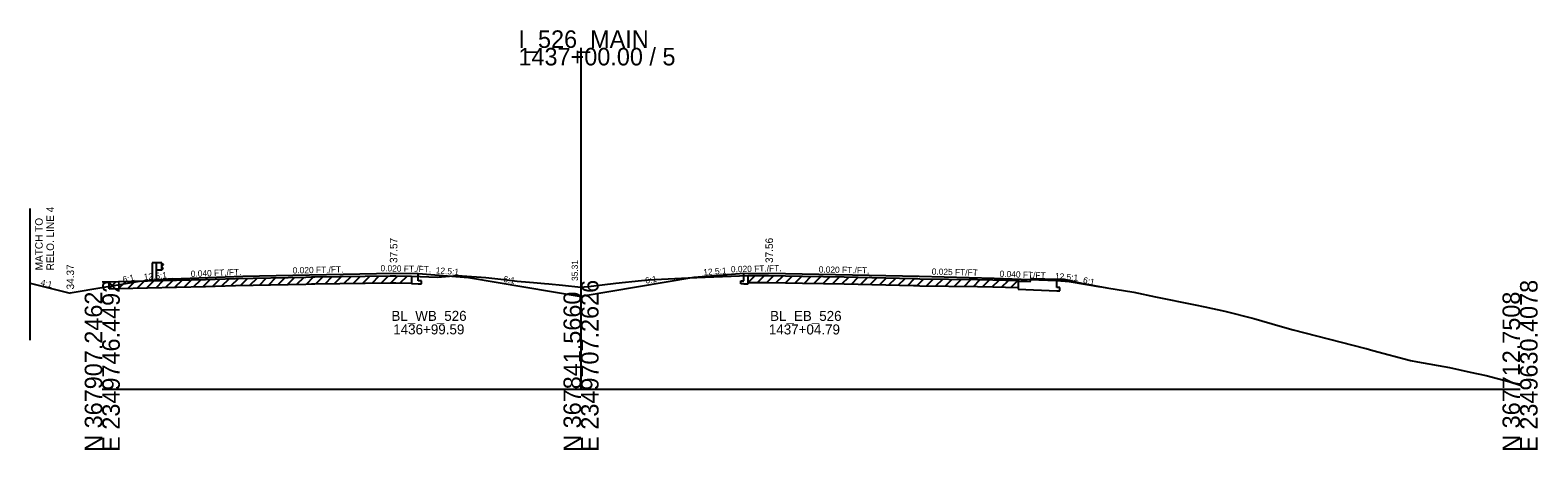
# Model space of a CAD drawing. Extents: x -170 to 2527928, y -10 to 1619750.
# Drawn here: x 4988.5 to 5229.3, y 2490.3 to 2557.4 of the extents above; entities that cross this region are included whole.
import ezdxf

# ---------------------------------------------------------------- set-up
doc = ezdxf.new("R2010")
doc.units = 0
for name, color, linetype in [('RD_GPK_XS_Cell', 7, 'Continuous'), ('RD_XS_Base', 7, 'Continuous'), ('RD_XS_EarthShd', 7, 'Continuous'), ('RD_XS_ExGround', 7, 'Continuous'), ('RD_XS_ExPaveRet', 7, 'Continuous'), ('RD_XS_GR', 7, 'Continuous'), ('RD_XS_MatchLine', 7, 'Continuous'), ('RD_XS_Pave', 7, 'Continuous'), ('RD_XS_PaveShd', 7, 'Continuous'), ('RD_XS_TieSlope', 7, 'Continuous'), ('RD_XS_TX_Elev_EX', 7, 'Continuous'), ('RD_XS_TX_Slope', 7, 'Continuous'), ('RD_XS_TX_Station', 7, 'Continuous')]:
    doc.layers.add(name, color=color, linetype=linetype)

msp = doc.modelspace()

# ---------------------------------------------------------------- linework, layer by layer
at = {"layer": 'RD_GPK_XS_Cell'}
for p, q in [((5076.48, 2500), (5076.48, 2554.57)), ((5000, 2500), (5076.48, 2500)), ((5076.48, 2500), (5226.48, 2500))]:
    msp.add_line(p, q, dxfattribs=at)
at = {"layer": 'RD_XS_Base'}
for p, q in [((5049.39, 2516.88), (5049.39, 2516.97)), ((5049.39, 2516.88), (5050.48, 2516.85)), ((5050.48, 2517.35), (5050.48, 2518.49)), ((5050.98, 2517.34), (5050.48, 2517.35)), ((5050.48, 2516.85), (5050.98, 2516.84)), ((5050.98, 2516.84), (5050.98, 2517.34)), ((5101.98, 2517.34), (5102.48, 2517.35)), ((5101.98, 2516.84), (5101.98, 2517.34)), ((5102.48, 2516.85), (5101.98, 2516.84)), ((5102.48, 2517.35), (5102.48, 2518.48)), ((5102.48, 2516.85), (5103.16, 2516.86)), ((5103.16, 2516.86), (5103.16, 2518.16)), ((5146.32, 2517.63), (5146.32, 2515.99)), ((5152.48, 2516.25), (5152.48, 2517.38)), ((5146.32, 2515.99), (5152.48, 2515.75)), ((5152.98, 2516.24), (5152.48, 2516.25)), ((5152.48, 2515.75), (5152.98, 2515.74)), ((5152.98, 2515.74), (5152.98, 2516.24))]:
    msp.add_line(p, q, dxfattribs=at)
at = {"layer": 'RD_XS_EarthShd'}
for p, q in [((5009.71, 2517.52), (5005.96, 2517.22)), ((5011.21, 2517.64), (5009.71, 2517.52)), ((5050.48, 2518.49), (5058.48, 2517.85)), ((5102.48, 2518.48), (5094.48, 2517.84))]:
    msp.add_line(p, q, dxfattribs=at)
at = {"layer": 'RD_XS_ExGround'}
msp.add_lwpolyline([(5000, 2517.17), (5002.59, 2517.22), (5016.51, 2517.53), (5018.01, 2517.59), (5021.3, 2517.71), (5032.5, 2517.93), (5033.41, 2517.95), (5033.97, 2517.96), (5046, 2518.14), (5046.9, 2518.13), (5049.39, 2518.09), (5053.57, 2517.91), (5056.75, 2518.16), (5061.25, 2517.85), (5064.63, 2517.5), (5066.26, 2517.3), (5068.24, 2517.12), (5068.88, 2517.07), (5070.66, 2516.9), (5071.34, 2516.84), (5073.5, 2516.62), (5076.45, 2516.31), (5078.1, 2516.5), (5082.05, 2516.96), (5086.15, 2517.39), (5087.23, 2517.5), (5093.59, 2517.8), (5103.16, 2518.16), (5104.96, 2518.18), (5106.44, 2518.19), (5111.87, 2518.09), (5118.52, 2517.96), (5129.6, 2517.7), (5130.29, 2517.68), (5130.62, 2517.67), (5139.81, 2517.54), (5142.27, 2517.47), (5146.33, 2517.36), (5146.47, 2517.3), (5146.53, 2517.28), (5147.75, 2517.26), (5148.24, 2517.25), (5148.36, 2517.58), (5148.41, 2517.71), (5148.52, 2517.71), (5148.8, 2517.71), (5152.38, 2517.58), (5153.64, 2517.58), (5156.44, 2516.96), (5160.48, 2516.2), (5164.8, 2515.52), (5168.26, 2514.78), (5174.56, 2513.51), (5176.1, 2513.15), (5179.33, 2512.5), (5183.93, 2511.29), (5188.17, 2510.07), (5190.24, 2509.5), (5201.62, 2506.56), (5201.82, 2506.51), (5201.91, 2506.49), (5202.94, 2506.21), (5208.97, 2504.61), (5210.08, 2504.38), (5215.19, 2503.5), (5218.5, 2502.75), (5221.04, 2502.17), (5224.71, 2501.24), (5226.48, 2500.67)], dxfattribs=at)
at = {"layer": 'RD_XS_ExPaveRet'}
for p, q in [((5001.1, 2516.07), (5002.24, 2517.21)), ((5001.1, 2516.07), (5001.1, 2517.19)), ((5002.6, 2516.1), (5003.75, 2517.25)), ((5004.1, 2516.13), (5005.25, 2517.28)), ((5005.6, 2516.17), (5006.75, 2517.31)), ((5007.1, 2516.2), (5008.25, 2517.35)), ((5008.6, 2516.23), (5009.75, 2517.38)), ((5010.1, 2516.27), (5011.25, 2517.41)), ((5011.6, 2516.3), (5012.75, 2517.45)), ((5013.1, 2516.33), (5014.25, 2517.48)), ((5014.6, 2516.37), (5015.75, 2517.51)), ((5016.1, 2516.4), (5017.26, 2517.56)), ((5017.6, 2516.45), (5018.76, 2517.62)), ((5019.1, 2516.51), (5020.26, 2517.67)), ((5020.6, 2516.56), (5021.76, 2517.71)), ((5021.3, 2516.58), (5032.5, 2516.81)), ((5022.1, 2516.6), (5023.24, 2517.75)), ((5023.6, 2516.63), (5024.74, 2517.78)), ((5025.1, 2516.66), (5026.24, 2517.81)), ((5026.6, 2516.69), (5027.74, 2517.84)), ((5028.1, 2516.72), (5029.24, 2517.87)), ((5029.6, 2516.75), (5030.74, 2517.9)), ((5031.1, 2516.78), (5032.24, 2517.93)), ((5032.5, 2516.81), (5033.41, 2516.83)), ((5032.6, 2516.82), (5033.74, 2517.96)), ((5033.41, 2516.83), (5033.97, 2516.84)), ((5033.97, 2516.84), (5046, 2517.02)), ((5034.1, 2516.84), (5035.24, 2517.98)), ((5035.6, 2516.86), (5036.74, 2518)), ((5037.1, 2516.89), (5038.24, 2518.03)), ((5038.6, 2516.91), (5039.74, 2518.05)), ((5040.1, 2516.93), (5041.24, 2518.07)), ((5041.6, 2516.95), (5042.74, 2518.09)), ((5043.1, 2516.98), (5044.24, 2518.12)), ((5044.6, 2517), (5045.74, 2518.14)), ((5046, 2517.02), (5046.9, 2517.01)), ((5046.1, 2517.02), (5047.2, 2518.12)), ((5046.9, 2517.01), (5049.39, 2516.97)), ((5047.6, 2517), (5048.7, 2518.1)), ((5049.39, 2518.09), (5049.39, 2516.97)), ((5103.16, 2517.04), (5104.29, 2518.17)), ((5103.16, 2517.04), (5103.16, 2518.16)), ((5103.16, 2517.04), (5104.96, 2517.06)), ((5104.66, 2517.06), (5105.79, 2518.19)), ((5104.96, 2517.06), (5106.44, 2517.07)), ((5106.16, 2517.07), (5107.27, 2518.17)), ((5106.44, 2517.07), (5111.87, 2516.97)), ((5107.66, 2517.05), (5108.76, 2518.15)), ((5109.16, 2517.02), (5110.26, 2518.12)), ((5110.66, 2516.99), (5111.76, 2518.09)), ((5111.87, 2516.97), (5118.52, 2516.84)), ((5112.16, 2516.96), (5113.26, 2518.06)), ((5113.66, 2516.93), (5114.76, 2518.03)), ((5115.16, 2516.9), (5116.26, 2518)), ((5116.66, 2516.87), (5117.76, 2517.97)), ((5118.16, 2516.84), (5119.26, 2517.94)), ((5118.52, 2516.84), (5129.6, 2516.57)), ((5119.66, 2516.81), (5120.75, 2517.91)), ((5121.16, 2516.78), (5122.25, 2517.87)), ((5122.66, 2516.74), (5123.75, 2517.83)), ((5124.16, 2516.7), (5125.25, 2517.8)), ((5125.66, 2516.67), (5126.75, 2517.76)), ((5127.16, 2516.63), (5128.25, 2517.73)), ((5128.66, 2516.6), (5129.75, 2517.69)), ((5130.16, 2516.56), (5131.26, 2517.66)), ((5131.66, 2516.54), (5132.76, 2517.64)), ((5133.16, 2516.52), (5134.26, 2517.62)), ((5134.66, 2516.49), (5135.76, 2517.6)), ((5136.16, 2516.47), (5137.26, 2517.58)), ((5137.66, 2516.45), (5138.76, 2517.56)), ((5139.16, 2516.43), (5140.26, 2517.53)), ((5140.66, 2516.4), (5141.75, 2517.49)), ((5142.16, 2516.35), (5143.25, 2517.45)), ((5143.66, 2516.31), (5144.75, 2517.4)), ((5145.16, 2516.27), (5146.25, 2517.36)), ((5146.33, 2517.36), (5146.33, 2516.24)), ((5001.1, 2516.07), (5002.59, 2516.1)), ((5002.59, 2516.1), (5016.51, 2516.41)), ((5016.51, 2516.41), (5018.01, 2516.47)), ((5018.01, 2516.47), (5021.3, 2516.58)), ((5129.6, 2516.57), (5130.29, 2516.56)), ((5130.29, 2516.56), (5130.62, 2516.55)), ((5130.62, 2516.55), (5139.81, 2516.42)), ((5139.81, 2516.42), (5142.27, 2516.35)), ((5142.27, 2516.35), (5146.33, 2516.24))]:
    msp.add_line(p, q, dxfattribs=at)
at = {"layer": 'RD_XS_GR'}
for p, q in [((5008.63, 2520.2), (5007.96, 2520.2)), ((5007.96, 2520.2), (5007.96, 2517.4)), ((5009.54, 2520.2), (5008.63, 2520.2)), ((5008.63, 2520.2), (5008.63, 2517.45)), ((5009.54, 2519.03), (5009.54, 2520.2)), ((5009.54, 2520.12), (5009.71, 2519.92)), ((5009.71, 2519.87), (5009.54, 2519.67)), ((5009.71, 2519.35), (5009.54, 2519.55)), ((5009.54, 2519.1), (5009.71, 2519.3)), ((5009.71, 2519.92), (5009.71, 2519.87)), ((5009.71, 2519.3), (5009.71, 2519.35)), ((5009.54, 2519.03), (5008.63, 2519.03))]:
    msp.add_line(p, q, dxfattribs=at)
at = {"layer": 'RD_XS_MatchLine'}
msp.add_line((4988.49, 2507.85), (4988.49, 2528.91), dxfattribs=at)
at = {"layer": 'RD_XS_Pave'}
for p, q in [((5022.48, 2518.09), (5046.48, 2518.57)), ((5106.48, 2518.56), (5130.48, 2518.08)), ((5130.48, 2518.08), (5142.48, 2517.78))]:
    msp.add_line(p, q, dxfattribs=at)
at = {"layer": 'RD_XS_PaveShd'}
for p, q in [((5011.21, 2517.64), (5022.48, 2518.09)), ((5011.21, 2517.43), (5011.21, 2517.64)), ((5046.48, 2518.57), (5050.48, 2518.49)), ((5102.48, 2518.48), (5106.48, 2518.56)), ((5142.48, 2517.78), (5152.48, 2517.38))]:
    msp.add_line(p, q, dxfattribs=at)
at = {"layer": 'RD_XS_TieSlope'}
for p, q in [((4988.48, 2516.96), (4994.85, 2515.37)), ((5005.96, 2517.22), (4994.85, 2515.37)), ((5058.48, 2517.85), (5076.5, 2514.85)), ((5094.48, 2517.84), (5076.5, 2514.85)), ((5152.48, 2517.38), (5154.48, 2517.22)), ((5154.48, 2517.22), (5159.47, 2516.39))]:
    msp.add_line(p, q, dxfattribs=at)

# ---------------------------------------------------------------- texts
at = {"layer": 'RD_GPK_XS_Cell'}
for s, p in [('I_526_MAIN', (5066.48, 2554.57)), ('1437+00.00 / 5', (5066.48, 2551.77))]:
    msp.add_text(s, height=2.8, dxfattribs=at).set_placement(p)
for s, p in [('E 2349746.4492', (5002.8, 2490)), ('E 2349707.2626', (5079.28, 2490)), ('E 2349630.4078', (5229.28, 2490)), ('N 367907.2462', (5000, 2490)), ('N 367841.5660', (5076.48, 2490)), ('N 367712.7508', (5226.48, 2490))]:
    msp.add_text(s, height=2.8, rotation=90, dxfattribs=at).set_placement(p)
at = {"layer": 'RD_XS_TX_Elev_EX'}
msp.add_text('35.31', height=1, rotation=90, dxfattribs=at).set_placement((5075.98, 2517.31))
at = {"layer": 'RD_XS_TX_Slope'}
for s, rotation, p in [('0.040 FT./FT.', 2.2906, (5014.16, 2517.94)), ('0.020 FT./FT.', 1.1458, (5030.43, 2518.5)), ('0.020 FT./FT.', 358.8542, (5044.44, 2518.86)), ('12.5:1', 355.4261, (5053.24, 2518.53)), ('12.5:1', 4.5739, (5096.06, 2518.19)), ('0.020 FT./FT.', 1.1458, (5100.43, 2518.69)), ('0.020 FT./FT.', 358.8542, (5114.44, 2518.66)), ('0.025 FT/FT', 358.5679, (5132.49, 2518.32)), ('4:1', 347.2181, (4990.08, 2516.62)), ('6:1', 12.4816, (5003.38, 2517.01)), ('12.5:1', 4.5739, (5006.66, 2517.45)), ('6:1', 350.5377, (5064.01, 2517.16)), ('6:1', 9.4623, (5086.81, 2516.86)), ('0.040 FT/FT', 357.7094, (5143.33, 2517.97)), ('12.5:1', 355.4261, (5152.15, 2517.61)), ('6:1', 346.8379, (5156.59, 2517.02))]:
    msp.add_text(s, height=1, rotation=rotation, dxfattribs=at).set_placement(p)
at = {"layer": 'RD_XS_TX_Station'}
for s, p in [('RELO. LINE 4', (4992.29, 2519.01)), ('MATCH TO', (4990.49, 2519.01)), (' 37.57', (5047.14, 2519.74)), (' 37.56', (5107.14, 2519.74)), ('34.37', (4995.5, 2515.95))]:
    msp.add_text(s, height=1.2, rotation=90, dxfattribs=at).set_placement(p)
for s, p in [('BL_WB_526', (5046.19, 2510.93)), ('BL_EB_526', (5106.68, 2510.92)), ('1436+99.59', (5046.48, 2508.77)), ('1437+04.79', (5106.48, 2508.76))]:
    msp.add_text(s, height=1.6, dxfattribs=at).set_placement(p)

doc.saveas('drawing.dxf')
